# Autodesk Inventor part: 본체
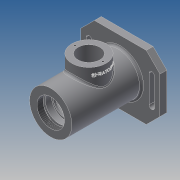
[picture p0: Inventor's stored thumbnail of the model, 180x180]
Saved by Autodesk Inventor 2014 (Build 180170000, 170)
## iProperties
Created: 2017-10
Part Number: 본체
Material: 일반
Document SubType Name: Modeling
Designer: NET
Density: 1 g/cm^3
Appearance: 기본값
Author: NET
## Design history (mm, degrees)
sketch "스케치6"
  geometry: L1 (0, 0)-(0, 115); L2 (-21, 0)-(-21, 9); L3 (-21, 9)-(-24, 9); L4 (-24, 9)-(-24, 12); L5 (-24, 12)-(-20, 12); L6 (-20, 12)-(-20, 21); L7 (-20, 21)-(-17.5, 21); L8 (-17.5, 21)-(-17.5, 24.25); L9 (-17.5, 24.25)-(-18.5, 24.25); L10 (-18.5, 24.25)-(-18.5, 26); L11 (-18.5, 26)-(-17.5, 26); L12 (-17.5, 26)-(-17.5, 37); L13 (-17.5, 37)-(-26, 37); L14 (-26, 37)-(-26, 75); L15 (-26, 75)-(-17.5, 75); L16 (-17.5, 75)-(-17.5, 86); L17 (-17.5, 86)-(-16.5, 86); L18 (-16.5, 86)-(-16.5, 91); L19 (-16.5, 91)-(-10, 91); L20 (-10, 91)-(-10, 93.7); L21 (-10, 93.7)-(-12.5, 93.7); L22 (-31, 115)-(-31, 0); L23 (-31, 0)-(-21, 0); L24 (-12.5, 93.7)-(-12.5, 100.3); L25 (-12.5, 100.3)-(-12.904, 101); L26 (-12.904, 101)-(-16, 101); L27 (-16, 101)-(-16, 115); L28 (-16, 115)-(-31, 115)
  constraints: 56 end point, 21 parallel, 5 perpendicular, 2 point on line, 1 collinear, 1 vertical
  dimensions: "d12" = 115 distance of L1.start L1.end; "d25" = 42 diameter of L2 L1; "d27" = 62 diameter of L22 L1; "d28" = 48 diameter of L4 L1; "d29" = 12 distance between parallel lines of L23 L5; "d30" = 3 distance between parallel lines of L5 L3; "d31" = 40 diameter of L6 L1; "d32" = 35 diameter of L8 L1; "d33" = 21 distance between parallel lines of L23 L7; "d34" = 26 distance between parallel lines of L23 L11; "d35" = 1.75 distance between parallel lines of L9 L11; "d36" = 37 diameter of L10 L1; "d37" = 11 distance between parallel lines of L13 L11; "d38" = 35 diameter of L12 L1; "d39" = 52 diameter of L14 L1; "d40" = 38 distance between parallel lines of L15 L13; "d41" = 11 distance between parallel lines of L15 L17; "d42" = 33 diameter of L18 L1; "d43" = 20 diameter of L20 L1; "d46" = 2.7 distance between parallel lines of L19 L21; "d48" = 25 diameter of L24 L1; "d49" = 0.7 vertical distance of L25.end L24.end; "d50" = 30 deg angle of L24 L25; "d51" = 7.3 distance between parallel lines of L26 L21; "d52" = 5 distance between parallel lines of L17 L19; "d57" = 32 diameter of L27 L1
revolve "회전1" sketch "스케치6" stored, may be unused: angle "d58" = 90 deg
sketch "스케치7"
  geometry: C1 r 21 at (0, 0) reference; C2 r 21 at (0, 0) reference; C3 r 31 at (0, 0) reference; C4 r 31 at (0, 0)
  constraints: 1 centre point, 1 coincident
  dimensions: "d59" = 62 diameter of C4
extrude "돌출2" join sketch "스케치7" distance "d60" = 9; taper "d61" = 0 deg
sketch "스케치8"
  geometry: C1 r 24 at (0, 0) reference; C2 r 31 at (0, 0) reference; 1 further point
  constraints: 1 coincident
hole "구멍2" sketch "스케치8" at (0, 0) diameter "d62" = 40.376; stored, may be unused: countersink angle "d66" = 90 deg, drill point angle "d68" = 0 deg; dims "d63" = 6, "d64" = 4, "d65" = 2, "d67" = 9
fillet "모깎기1" dims "d69" = 3
chamfer "모따기1" distance "d70" = 1; stored, may be unused: second distance "d71" = 2, angle "d72" = 45 deg
fillet "모깎기2" dims "d73" = 0.3
fillet "모깎기3" dims "d74" = 3
sketch "스케치10"
  geometry: L1 (0, 0)-(0, 115); L2 (16, 115)-(-16, 115) reference; L3 (31, 115)-(-31, 115) reference; L4 (12.5, 100.3)-(-12.5, 100.3) reference; L5 (-16, 101)-(-22, 115); L6 (-16, 101)-(-16, 115); L7 (16, 101)-(-16, 101) reference
  constraints: 6 end point, 2 perpendicular, 1 midpoint, 1 point on line
  dimensions: "d77" = 32 diameter of L5.start L1; "d78" = 44 diameter of L5.end L1; "d79" = 14 distance from line of L2 L5.start
revolve "회전2" sketch "스케치10" stored, may be unused: angle "d80" = 90 deg
fillet "모깎기4" dims "d81" = 0.3
sketch "스케치11"
  geometry: C1 r 31 at (0, 0) reference; C2 r 35 at (0, 0)
  constraints: 1 centre point, 1 coincident
  dimensions: "d82" = 70 diameter of C2
extrude "돌출3" join sketch "스케치11" distance "d83" = 3; taper "d84" = 0 deg
node "작업 평면1"
sketch "스케치12"
  geometry: L1 (-58, -47)-(58, -47); L2 (58, -47)-(58, 47); L3 (58, 47)-(-58, 47); L4 (-58, 47)-(-58, -47); L5 (-58, -47)-(58, 47); L6 (58, -47)-(-58, 47); L7 (0, -47)-(0, 47); L8 (-58, 0)-(58, 0); L9 (-46, 20)-(-46, -20); L10 (-42, 20)-(-42, -20); L11 (-50, -20)-(-50, 20); L12 (42, 20)-(42, -20); L13 (50, -20)-(50, 20); C1 r 35 at (0, 0) reference; C2 r 22 at (0, 0) reference; C3 r 22 at (0, 0) reference; A1 r 4 centre (-46, 20) between (-42, 20) and (-50, 20); A2 r 4 centre (-46, -20) between (-50, -20) and (-42, -20); A3 r 4 centre (46, 20) between (50, 20) and (42, 20); A4 r 4 centre (46, -20) between (42, -20) and (50, -20); 3 further points
  constraints: 28 end point, 8 midpoint, 8 point on circle, 6 symmetric about line, 4 centre point, 4 parallel, 4 tangent, 1 horizontal, 1 horizontal alignment, 1 perpendicular, 2 other
  dimensions: "d86" = 94 distance between parallel lines of L1 L3; "d87" = 116 distance between parallel lines of L4 L2; "d88" = 46 distance between parallel lines of L7 L9; "d89" = 20 distance of point (-46, 0) L9.end; "d90" = 4 radius of A2
extrude "돌출4" join sketch "스케치12" distance "d91" = 10; taper "d92" = 0 deg
fillet "모깎기5" dims "d93" = 3
node "작업 평면2"
sketch "스케치13"
  geometry: L1 (31, 0)-(-31, 0) reference; C1 r 25 at (0, 56); 1 further point
  constraints: 1 centre point, 1 vertical alignment
  dimensions: "d95" = 50 diameter of C1; "d96" = 56 distance from line of L1 C1.centre
extrude "돌출5" join sketch "스케치13" stored distance "d97" = 10; taper "d98" = 0 deg
sketch "스케치14"
  geometry: C1 r 25 at (0, 0) reference; C2 r 16 at (0, 0); 1 further point
  constraints: 1 centre point, 1 coincident
  dimensions: "d99" = 32 diameter of C2
extrude "돌출6" cut sketch "스케치14" stored distance "d100" = 10; taper "d101" = 0 deg
sketch "스케치15"
  geometry: C1 r 16 at (0, 0) reference; C2 r 25 at (0, 0) reference; A1 r 20.5 centre (0, 0) between (-20.5, 0) and (20.5, 0); 1 further point
  constraints: 2 horizontal alignment, 2 point on circle, 1 centre point, 1 coincident
  dimensions: "d102" = 41 diameter of A1
hole "구멍3" sketch "스케치15" at (-20.5, 0), (20.5, 0) diameter "d103" = 2.459; stored, may be unused: countersink angle "d107" = 82 deg, drill point angle "d109" = 118 deg; dims "d104" = 6, "d105" = 3.023, "d106" = 2, "d108" = 8
fillet "모깎기6" dims "d110" = 3
node "작업 평면3"
sketch "스케치16"
  geometry: L1 (37.909, 42.108)-(74.091, 42.108); L2 (74.091, 42.108)-(74.091, 31.892); L3 (74.091, 31.892)-(37.909, 31.892); L4 (37.909, 31.892)-(37.909, 42.108); L5 (37.909, 37)-(74.091, 37); L6 (56, 42.108)-(56, 31.892); L7 (0, -31)-(0, 31) reference; L8 (31, 47)-(81, 47) reference; 1 further point
  constraints: 4 end point, 4 midpoint, 2 other
  dimensions: "d112" = 56 distance between parallel lines of L7 L6; "d113" = 10 distance between parallel lines of L8 L5
feature "엠보싱1" sketch "스케치16" dims "d12" = 115, "d25" = 42, "d27" = 62, "d28" = 48, "d29" = 12, "d30" = 3, "d31" = 40, "d32" = 35, "d33" = 21, "d34" = 26, "d35" = 1.75, "d36" = 37, "d37" = 11, "d38" = 35, "d39" = 52, "d40" = 38, "d41" = 11, "d42" = 33, "d43" = 20, "d46" = 2.7, "d48" = 25, "d49" = 0.7, "d50" = 30 deg, "d51" = 7.3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
chamfer "모따기2" distance "d116" = 20; stored, may be unused: second distance "d117" = 2, angle "d118" = 45 deg
node "솔리드2"
node "투영된 루프2"
node "투영된 루프3"
node "투영된 루프4"
other parameters: "d85" = 112, "d94" = 47
